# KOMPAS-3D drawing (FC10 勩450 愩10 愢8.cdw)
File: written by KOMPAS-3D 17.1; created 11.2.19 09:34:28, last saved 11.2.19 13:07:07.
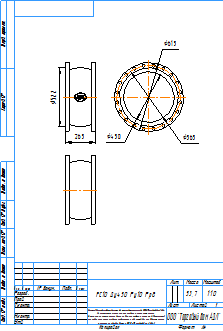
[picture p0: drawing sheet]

Sheet 1: A4, portrait

Title block, sheet 1: name: FC10 Ду450 Ру10 Рр8; mass: 53,7; sheets: 1; sheet format: A4; stored path: \\adlc.lan\data\АДЛ_ПКД\3D-модели\ADL production\Гибкие вставки серии FC\FC10\KOMPAS 2D\FC10 Ду450 Ру10 Рр8.cdw

Views: Вид 1
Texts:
  kka
  adl
  Рама для чертежей
  Лит-Масса-Масштаб
  Материал-Предприятие
  Масштаб
  Изм.
  Лист
  № докум.
  Подп.
  Дата
  Лит.
  Разраб.
  Пров.
  Т.контр.
  Листов
  Внимание! Данный продукт является объектом авторского права ООО «Торговый Дом АДЛ».
  Запрещается изменение, копирование, распространение
  (в том числе путем копирования на другие сайты и ресурсы в Интернете)
  или любое иное использование информации и объектов без предварительного
  согласия правообладателя (ООО «Торговый Дом АДЛ»).
  Н.контр.
  Утв.
  ООО "Торговый дом АДЛ"
  Изменение
  Номер документа
  Подпись
  Обозначение документа
  Наименование изделия
  Масса изделия по ГОСТ 2.109-73
  Порядковый номер листа
  Общее количество листов в документе
  Характер работы, выполненной лицом, подписавшим документ
  Наименование или индекс предприятия, выпускающего документ
  Инв. № подл.
  Подп. и дата
  Взам. инв. №
  Инв. № дубл.
  Инвентарный номер подлинника по ГОСТ 2.501-68
  Подпись принявшего подлинник в отдел технической документации
  Инвентарный номер подлинника, взамен которого выпущен данный подлинник
  Инвентарный номер дубликата по ГОСТ 2.502-68
  Подпись принявшего дубликат в отдел технической документации
  Справ. №
  Перв. примен.
  Обозначение документа, взамен или на основании которого выпущен данный документ
  Обозначение документа, в котором впервые записан данный документ
  Подпись лица, копировавшего чертеж
  Обозначение формата листа
  !Рама для чертежа
Dimensions and other numbers on the sheet: 265; 522; 450; 565; 615; 1:10; 1; 53,7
